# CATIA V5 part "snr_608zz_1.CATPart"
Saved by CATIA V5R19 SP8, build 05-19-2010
Part number: snr_608zz_1_1
Nomenclature: 70_i
Source: Unknown
Description: PART-snr_608zz_1_1-DESC
Bounding box of the stored display mesh (mm): x 0 to 7, y -11 to 11, z -11 to 11
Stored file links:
  C:\Users\rphgr\Desktop\0_Tapis_TC520B_vitesse\snr_608zz_1.CATPart
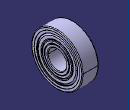
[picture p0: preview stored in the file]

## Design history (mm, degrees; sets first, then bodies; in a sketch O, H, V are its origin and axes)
Body1 "snr_608zz_1_1" (main body)
  Solid1: solid without history
  AxisSystem1: origin (0, 0, 0), X (1, 0, 0), Y (0, 1, 0), Z (0, 0, 1)
Body2 "snr_608zz_1_2"
  Solid2: solid without history
Body3 "snr_608zz_1_3"
  Solid3: solid without history
Body4 "snr_608zz_1_4"
  Solid4: solid without history
Body5 "snr_608zz_1_5"
  Solid5: solid without history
